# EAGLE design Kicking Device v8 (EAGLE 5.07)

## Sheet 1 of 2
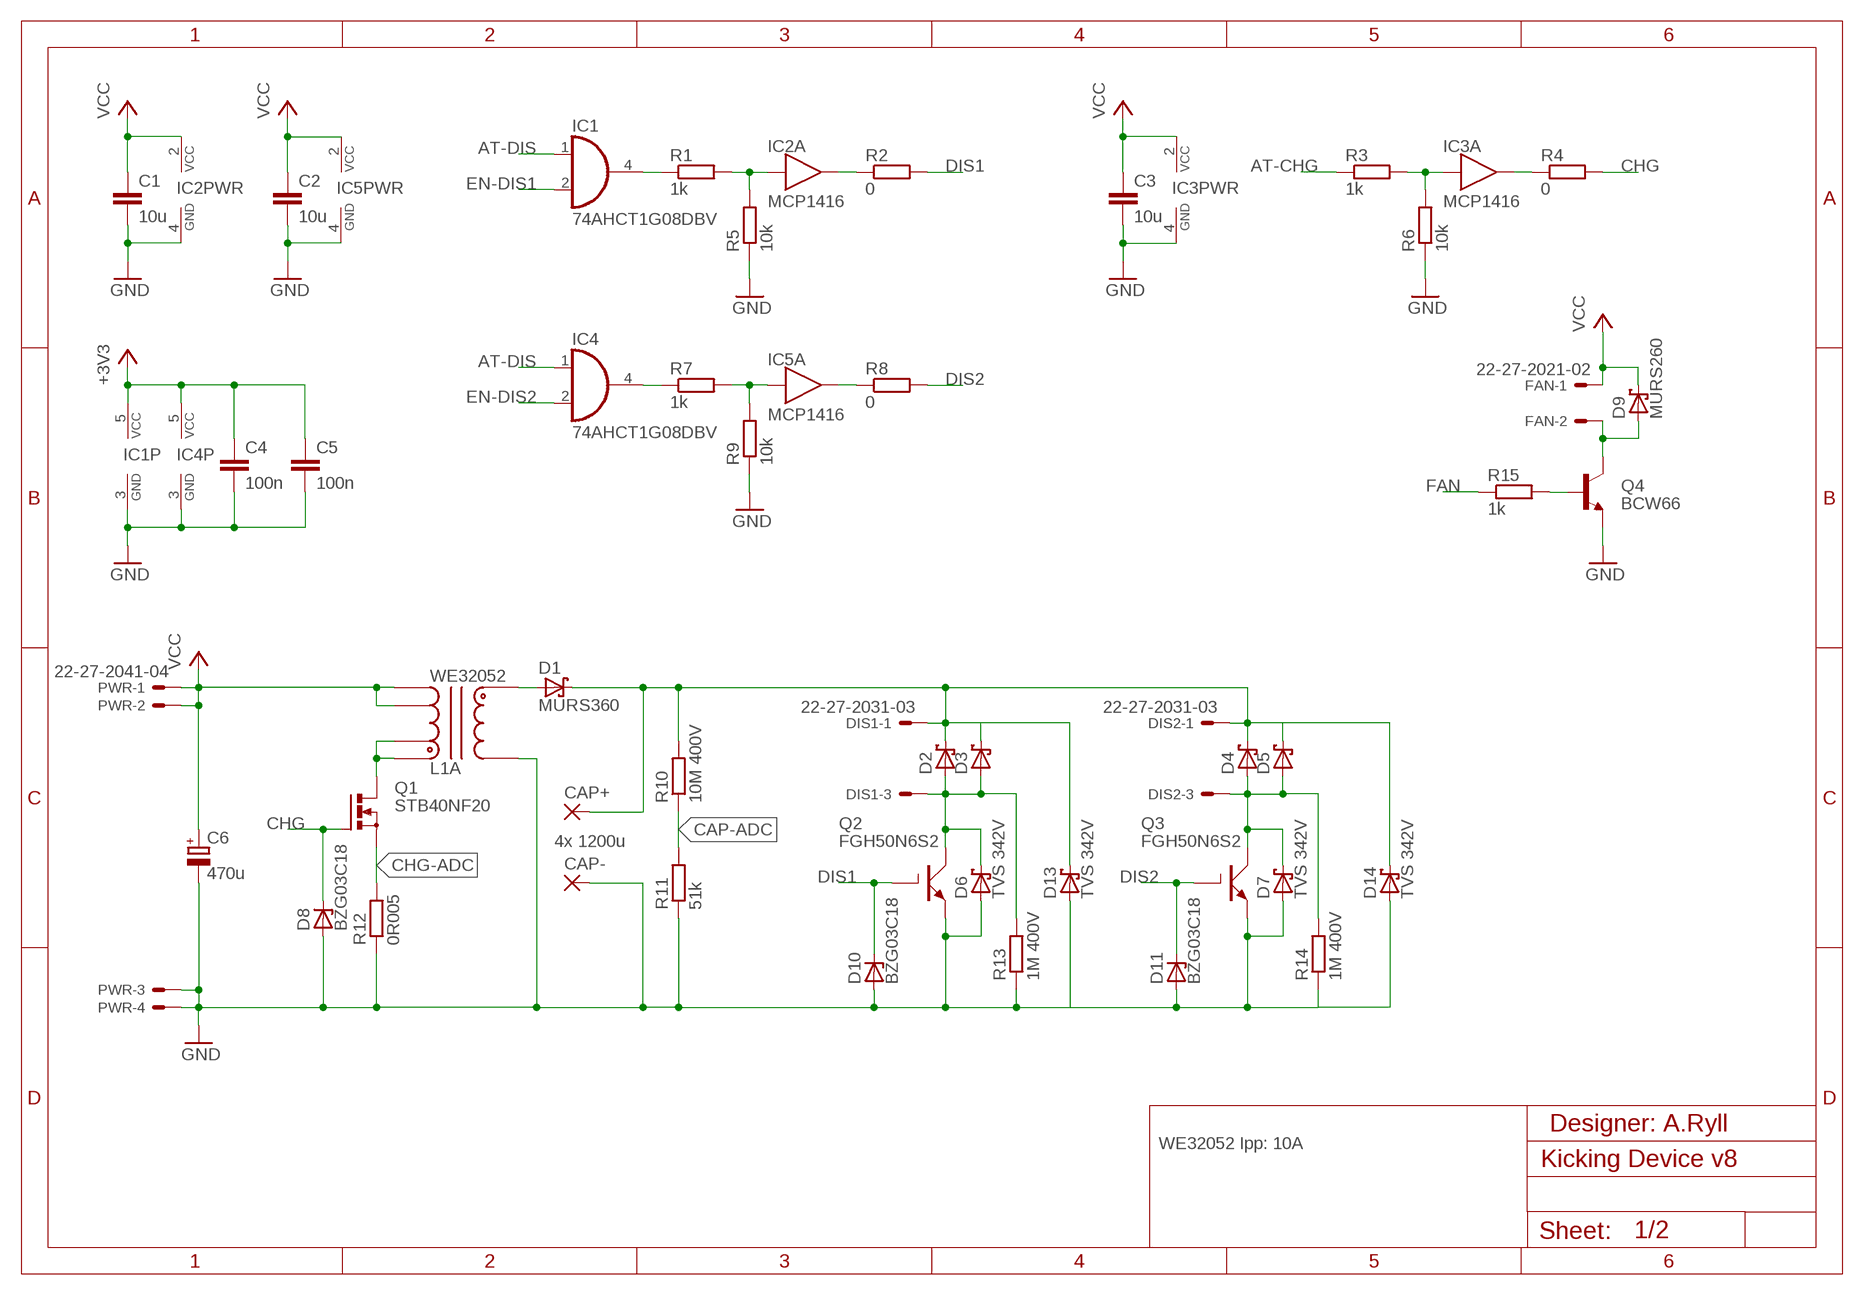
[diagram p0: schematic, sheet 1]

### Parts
C1  10u  C-EUC0805  [C0805]
C2  10u  C-EUC0805  [C0805]
C3  10u  C-EUC0805  [C0805]
C4  100n  C-EUC0805  [C0805]
C5  100n  C-EUC0805  [C0805]
C6  470u  CPOL-EUG  [PANASONIC_G]
CAP+  WIREPAD3,17/1,3  WIREPAD2,54/1,5  [2,54/1,5]
CAP-  WIREPAD3,17/1,3  WIREPAD2,54/1,5  [2,54/1,5]
D1  MURS360  SCHOTTKY-DIODESMC  [SMC]
D2  SCHOTTKY-DIODEAC  [TO247AC]
D3  SCHOTTKY-DIODEAC  [TO247AC]
D4  SCHOTTKY-DIODEAC  [TO247AC]
D5  SCHOTTKY-DIODEAC  [TO247AC]
D6  TVS 342V  SCHOTTKY-DIODESMD  [SMB]
D7  TVS 342V  SCHOTTKY-DIODESMD  [SMB]
D8  BZG03C18  ZENER-DIODESMB  [SMB]
D9  MURS260  SCHOTTKY-DIODESMD  [SMB]
D10  BZG03C18  ZENER-DIODESMB  [SMB]
D11  BZG03C18  ZENER-DIODESMB  [SMB]
D13  TVS 342V  SCHOTTKY-DIODESMD  [SMB]
D14  TVS 342V  SCHOTTKY-DIODESMD  [SMB]
DIS1  22-27-2031-03  [6410-03]
DIS2  22-27-2031-03  [6410-03]
FAN  22-27-2021-02  [6410-02]
IC1  74AHCT1G08DBV  [SOT23-5]
IC2  MCP1416  [SOT23-5]
IC3  MCP1416  [SOT23-5]
IC4  74AHCT1G08DBV  [SOT23-5]
IC5  MCP1416  [SOT23-5]
L1  WE32052  [WE32052]
PWR  22-27-2041-04  [6410-04]
Q1  STB40NF20  NMOS-D2PAK  [D2PAK]
Q2  FGH50N6S2  IGBT-TO247  [TO247BV]
Q3  FGH50N6S2  IGBT-TO247  [TO247BV]
Q4  BCW66  BCW60SMD  [SOT23-BEC]
R1  1k  R-EU_R0805  [R0805]
R2  0  R-EU_R0805  [R0805]
R3  1k  R-EU_R0805  [R0805]
R4  0  R-EU_R0805  [R0805]
R5  10k  R-EU_R0805  [R0805]
R6  10k  R-EU_R0805  [R0805]
R7  1k  R-EU_R0805  [R0805]
R8  0  R-EU_R0805  [R0805]
R9  10k  R-EU_R0805  [R0805]
R10  10M 400V  R-EU_R1206  [R1206]
R11  51k  R-EU_R0805  [R0805]
R12  0R005  R-EU_R2512  [R2512]
R13  1M 400V  R-EU_R1206  [R1206]
R14  1M 400V  R-EU_R1206  [R1206]
R15  1k  R-EU_R0805  [R0805]

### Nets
400-HIGH: D1.A L1.1
+3V3: C4.1 C5.1 IC1.5(VCC) IC4.5(VCC) ; also sheet 2
AT-CHG: R3.1 ; also sheet 2
AT-DIS: IC1.1(I0) IC4.1(I0) ; also sheet 2
CAP-ADC: R10.1 R11.2 ; also sheet 2
CAPVCC [HV]: CAP+.P$1(P) D1.C D2.1(C) D3.1(C) D4.1(C) D5.1(C) D13.C D14.C DIS1.1 DIS2.1 R10.2
CHG: D8.C Q1.1(G) R4.2
CHG-: L1.6 L1.7 Q1.2(D)
CHG-ADC: Q1.3(S) R12.2 ; also sheet 2
DIS1: D10.C Q2.1(G) R2.2
DIS1-SW [HV]: D2.3(A) D3.3(A) D6.C DIS1.3 Q2.2(C) R13.2
DIS2: D11.C Q3.1(G) R8.2
DIS2-SW [HV]: D4.3(A) D5.3(A) D7.C DIS2.3 Q3.2(C) R14.2
EN-DIS1: IC1.2(I1) ; also sheet 2
EN-DIS2: IC4.2(I1) ; also sheet 2
FAN: R15.1 ; also sheet 2
GND: C1.2 C2.2 C3.2 C4.2 C5.2 C6.- CAP-.P$1(P) D6.A D7.A D8.A D10.A D11.A D13.A D14.A IC1.3(GND) IC2.4(PWR:GND) IC3.4(PWR:GND) IC4.3(GND) IC5.4(PWR:GND) L1.10 PWR.3 PWR.4 Q2.3(E) Q3.3(E) Q4.E R5.1 R6.1 R9.1 R11.1 R12.1 R13.1 R14.1 ; also sheet 2
N$1: IC1.4(O) R1.1
N$2: IC2.3(A:IN) R1.2 R5.2
N$3: IC3.3(A:IN) R3.2 R6.2
N$5: IC2.5(A:OUT) R2.1
N$6: D9.A FAN.2 Q4.C
N$11: IC5.3(A:IN) R7.2 R9.2
N$12: Q4.B R15.2
N$13: IC4.4(O) R7.1
N$17: IC5.5(A:OUT) R8.1
N$19: IC3.5(A:OUT) R4.1
VCC: C1.1 C2.1 C3.1 C6.+ D9.C FAN.1 IC2.2(PWR:VCC) IC3.2(PWR:VCC) IC5.2(PWR:VCC) L1.4 L1.5 PWR.1 PWR.2
Unconnected: DIS1.2 DIS2.2

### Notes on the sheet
- 4x 1200u
- Designer: A.Ryll
- WE32052 Ipp: 10A

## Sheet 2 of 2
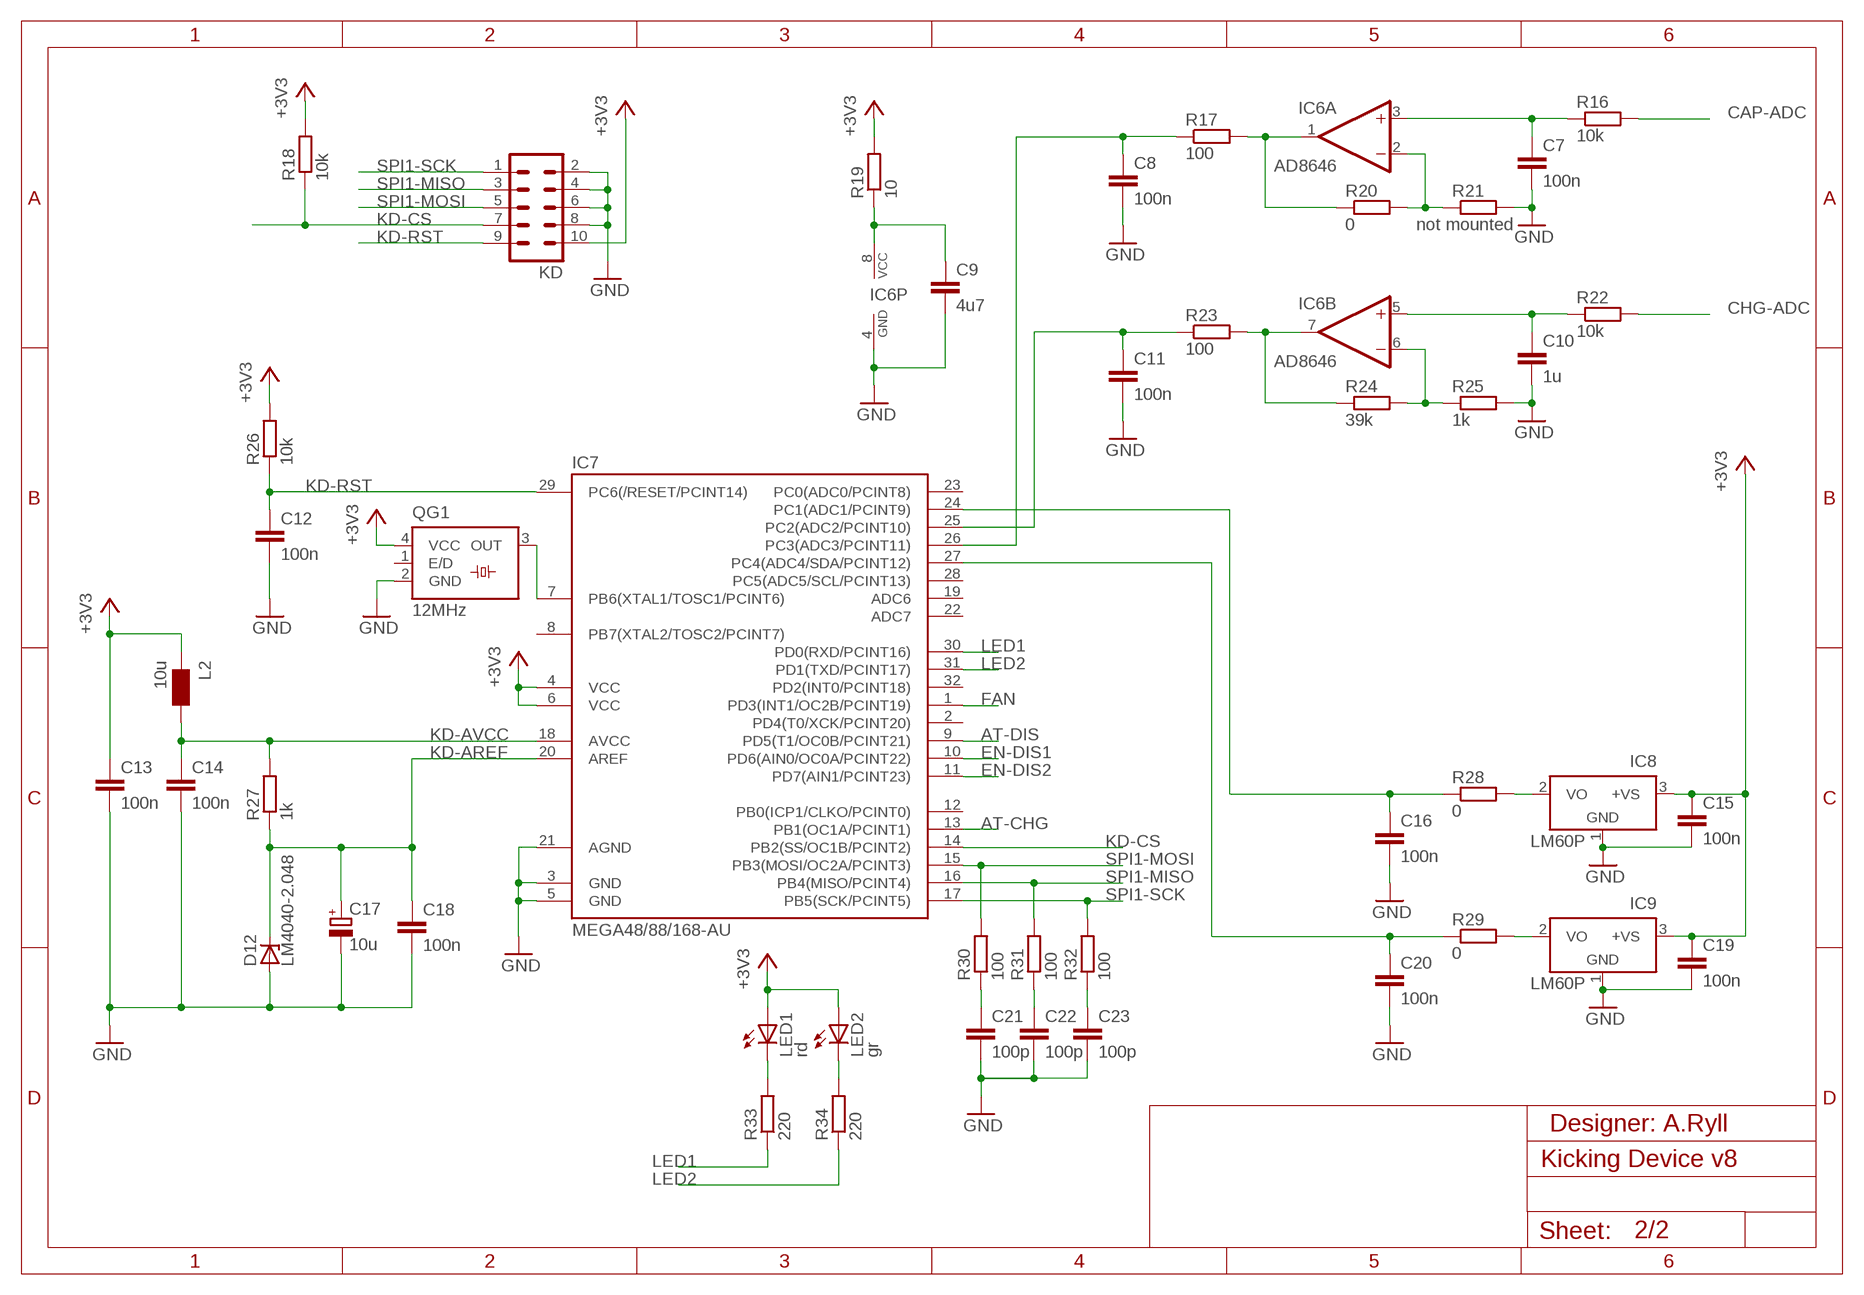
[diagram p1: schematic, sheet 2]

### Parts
C7  100n  C-EUC0805  [C0805]
C8  100n  C-EUC0805  [C0805]
C9  4u7  C-EUC0805  [C0805]
C10  1u  C-EUC0805  [C0805]
C11  100n  C-EUC0805  [C0805]
C12  100n  C-EUC0805  [C0805]
C13  100n  C-EUC0805  [C0805]
C14  100n  C-EUC0805  [C0805]
C15  100n  C-EUC0805  [C0805]
C16  100n  C-EUC0805  [C0805]
C17  10u  CPOL-EUC/6032-28W  [C/6032-28W]
C18  100n  C-EUC0805  [C0805]
C19  100n  C-EUC0805  [C0805]
C20  100n  C-EUC0805  [C0805]
C21  100p  C-EUC0805  [C0805]
C22  100p  C-EUC0805  [C0805]
C23  100p  C-EUC0805  [C0805]
D12  LM4040-2.048  ZENER-DIODELM4040  [SOT23]
IC6  AD8646  AD-OP2S  [SOIC8]
IC7  MEGA48/88/168-AU  [TQFP32-08]
IC8  LM60P  [TO92]
IC9  LM60P  [TO92]
KD  ML10  [ML10]
L2  10u  WE-MI_0805  [0805]
LED1  rd  LEDCHIP-LED0805  [CHIP-LED0805]
LED2  gr  LEDCHIP-LED0805  [CHIP-LED0805]
QG1  12MHz  SM77H  [SM77H]
R16  10k  R-EU_R0805  [R0805]
R17  100  R-EU_R0805  [R0805]
R18  10k  R-EU_R0805  [R0805]
R19  10  R-EU_R0805  [R0805]
R20  0  R-EU_R0805  [R0805]
R21  not mounted  R-EU_R0805  [R0805]
R22  10k  R-EU_R0805  [R0805]
R23  100  R-EU_R0805  [R0805]
R24  39k  R-EU_R0805  [R0805]
R25  1k  R-EU_R0805  [R0805]
R26  10k  R-EU_R0805  [R0805]
R27  1k  R-EU_R0805  [R0805]
R28  0  R-EU_R0805  [R0805]
R29  0  R-EU_R0805  [R0805]
R30  100  R-EU_R0805  [R0805]
R31  100  R-EU_R0805  [R0805]
R32  100  R-EU_R0805  [R0805]
R33  220  R-EU_R0805  [R0805]
R34  220  R-EU_R0805  [R0805]

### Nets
+3V3: C13.1 C15.1 C19.1 IC7.4(VCC) IC7.6(VCC) IC8.3(+VS) IC9.3(+VS) KD.10 L2.1 LED1.A LED2.A QG1.4(VCC) R18.2 R19.2 R26.2 ; also sheet 1
AT-CHG: IC7.13(PB1(OC1A/PCINT1)) ; also sheet 1
AT-DIS: IC7.9(PD5(T1/OC0B/PCINT21)) ; also sheet 1
CAP-ADC: R16.2 ; also sheet 1
CHG-ADC: R22.2 ; also sheet 1
EN-DIS1: IC7.10(PD6(AIN0/OC0A/PCINT22)) ; also sheet 1
EN-DIS2: IC7.11(PD7(AIN1/PCINT23)) ; also sheet 1
FAN: IC7.1(PD3(INT1/OC2B/PCINT19)) ; also sheet 1
GND: C7.2 C8.2 C9.2 C10.2 C11.2 C12.2 C13.2 C14.2 C15.2 C16.2 C17.- C18.2 C19.2 C20.2 C21.2 C22.2 C23.2 D12.2(A) IC6.4(P:GND) IC7.3(GND) IC7.5(GND) IC7.21(AGND) IC8.1(GND) IC9.1(GND) KD.2 KD.4 KD.6 KD.8 QG1.2(GND) R21.2 R25.2 ; also sheet 1
KD-AREF: C17.+ C18.1 D12.1(C) IC7.20(AREF) R27.1
KD-AVCC: C14.1 IC7.18(AVCC) L2.2 R27.2
KD-CS: IC7.14(PB2(SS/OC1B/PCINT2)) KD.7 R18.1
KD-RST: C12.1 IC7.29(PC6(/RESET/PCINT14)) KD.9 R26.1
LED1: IC7.30(PD0(RXD/PCINT16)) R33.1
LED2: IC7.31(PD1(TXD/PCINT17)) R34.1
N$4: LED1.C R33.2
N$8: LED2.C R34.2
N$10: IC8.2(VO) R28.2
N$14: IC9.2(VO) R29.2
N$15: C9.1 IC6.8(P:VCC) R19.1
N$18: C21.1 R30.1
N$23: C7.1 IC6.3(A:+IN) R16.1
N$24: IC6.1(A:OUT) R17.2 R20.1
N$25: IC6.2(A:-IN) R20.2 R21.1
N$28: C16.1 IC7.24(PC1(ADC1/PCINT9)) R28.1
N$31: C22.1 R31.1
N$32: C20.1 IC7.27(PC4(ADC4/SDA/PCINT12)) R29.1
N$36: C8.1 IC7.26(PC3(ADC3/PCINT11)) R17.1
N$38: C23.1 R32.1
N$39: C10.1 IC6.5(B:+IN) R22.1
N$40: IC6.6(B:-IN) R24.2 R25.1
N$41: C11.1 IC7.25(PC2(ADC2/PCINT10)) R23.1
N$42: IC6.7(B:OUT) R23.2 R24.1
SPI1-MISO: IC7.16(PB4(MISO/PCINT4)) KD.3 R31.2
SPI1-MOSI: IC7.15(PB3(MOSI/OC2A/PCINT3)) KD.5 R30.2
SPI1-SCK: IC7.17(PB5(SCK/PCINT5)) KD.1 R32.2
XTAL: IC7.7(PB6(XTAL1/TOSC1/PCINT6)) QG1.3(OUT)
Unconnected: IC7.2(PD4(T0/XCK/PCINT20)) IC7.8(PB7(XTAL2/TOSC2/PCINT7)) IC7.12(PB0(ICP1/CLKO/PCINT0)) IC7.19(ADC6) IC7.22(ADC7) IC7.23(PC0(ADC0/PCINT8)) IC7.28(PC5(ADC5/SCL/PCINT13)) IC7.32(PD2(INT0/PCINT18)) QG1.1(E/D)

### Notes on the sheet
- Designer: A.Ryll

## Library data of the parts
C1-C5 C7-C16 C18-C23 = rcl:C-EU: CAPACITOR, European symbol
C6 C17 = rcl:CPOL-EU: POLARIZED CAPACITOR, European symbol
CAP+ CAP- = Marvin:WIREPAD: Wire PAD connect wire on PCB
D1 D6 D7 D9 D13 D14 = diode:SCHOTTKY-DIODE: Schottky Diode
D2-D5 = Marvin:SCHOTTKY-DIODE: Schottky Diode
D8 D10 D11 = diode:ZENER-DIODE: Z-Diode
D12 = Marvin:ZENER-DIODE: Z-Diode
DIS1 DIS2 = con-molex:22-?-03: CONNECTOR wire to board 2.54 mm (.1 inch) pitch header
FAN = con-molex:22-?-02: CONNECTOR
IC1 IC4 = 74xx-little-de:74*1G08: 2-input AND gate
IC2 IC3 IC5 = Marvin:MCP1416
IC6 = Marvin:AD-OP2
IC7 = avr-6:MEGA48/88/168
IC8 IC9 = Marvin:LM60: LM60 Temperature Sensor -40°C to 125°C
KD = con-harting-ml:ML10: HARTING
L1 = Marvin:WE32052
L2 = wuerth-elektronik:WE-MI: SMD Multilayer Inductor WE-MI
LED1 LED2 = led:LED: LED
PWR = con-molex:22-?-04: CONNECTOR wire to board 2.54 mm (.1 inch) pitch header
Q1 = Marvin:NMOS-D2PAK
Q2 Q3 = Marvin:IGBT-TO247
Q4 = transistor-npn:BCW60*: NPN Transistor
QG1 = Marvin:SM77H: 3.3V CMOS Clock Oscillator Source: www.pletronics.com .. sm77h%203.3v.pdf
R1-R34 = rcl:R-EU_: RESISTOR, European symbol

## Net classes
0 default: width 0.152 mm, clearance 0.152 mm
1 HV: width 0.254 mm, drill 0.305 mm, clearance 1.524 mm to class 0, clearance 1.524 mm

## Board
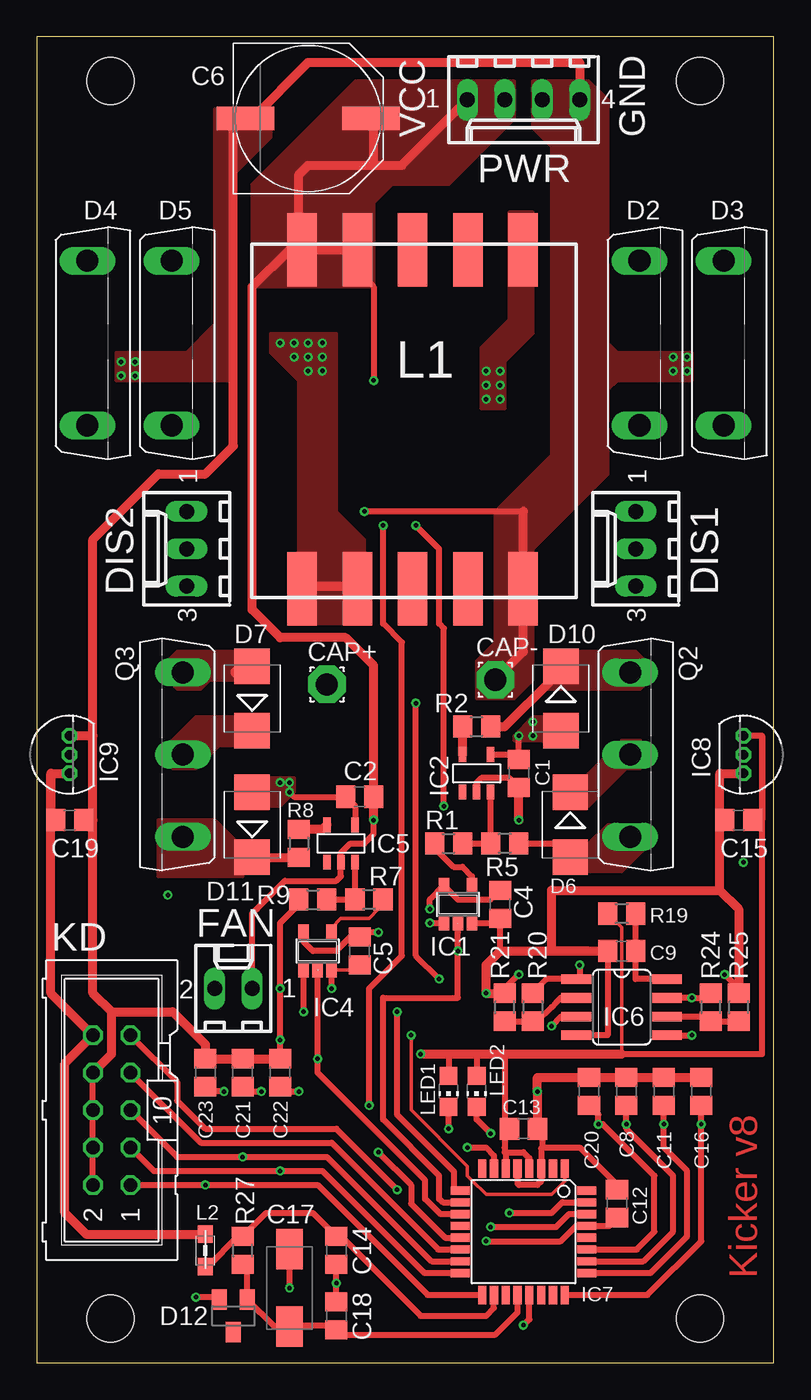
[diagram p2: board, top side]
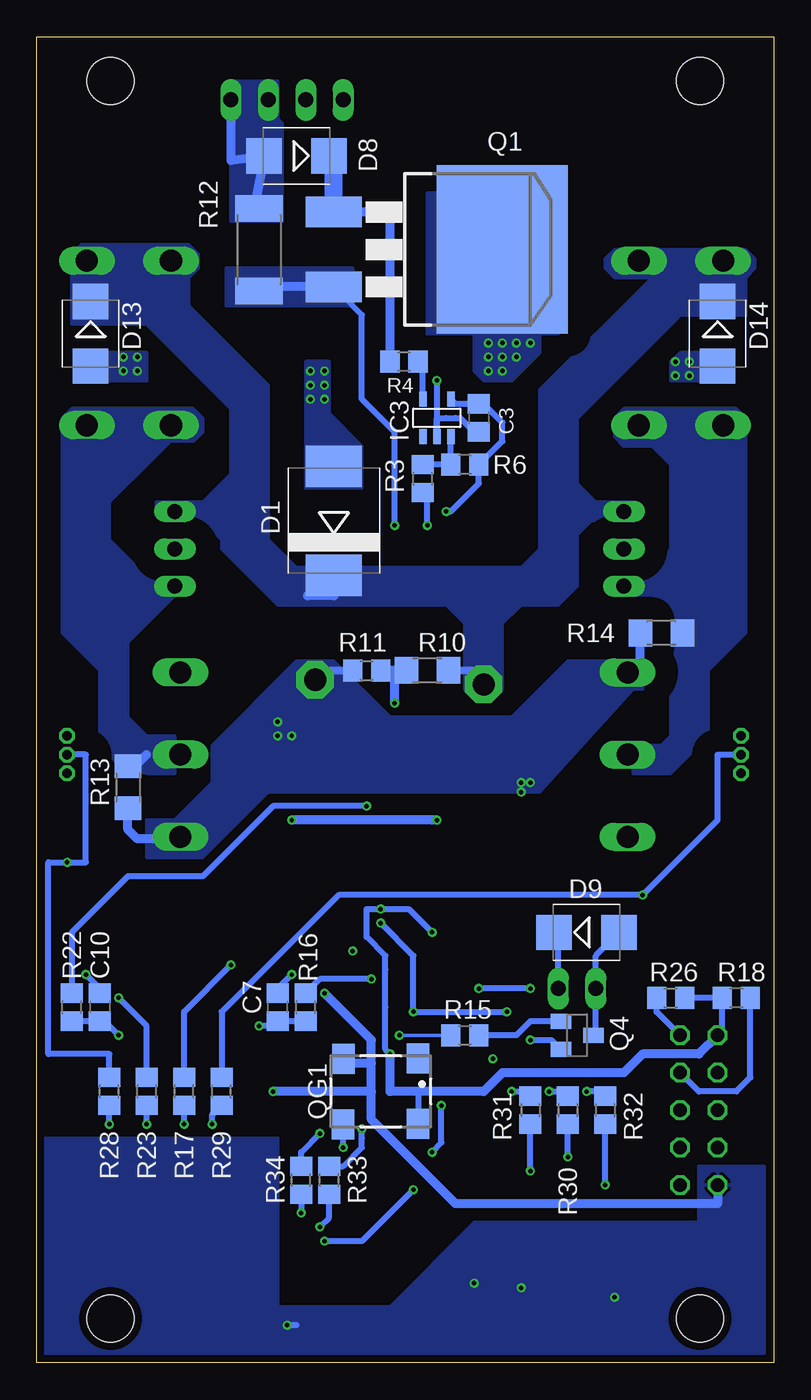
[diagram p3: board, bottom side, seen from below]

Size 50 x 90 mm. Coordinates in mm from the lower left corner, seen from the top.
Outline: 0,0 50,0 50,90 0,90 0,0
Copper layers (1*16): Top 0.035mm / dielectric 1.5mm / Bottom 0.035mm
Design rules "PCB-POOL *": minimum track width 6mil, minimum drill 12mil, track to track 6mil, track to pad 6mil, pad to pad 6mil, via to via 6mil, smd to smd 6mil, copper to edge 20mil, drill to drill 8mil, minimum pad ring 8mil, minimum via ring 6mil, stop-mask expansion 3mil, vias tented up to drill 0mil, thermal gap 8mil
Holes 3.2 mm at 45,3 5,3 5,87 45,87

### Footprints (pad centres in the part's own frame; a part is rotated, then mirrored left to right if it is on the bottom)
C0805 = smd 1.3 x 1.5: 1 -0.95,0; 2 0.95,0
PANASONIC_G = smd 3.9 x 1.6: + 4.25,0; - -4.25,0
C/6032-28W = smd 2.75 x 1.8: + 2.625,0; - -2.625,0
2,54/1,5 = drill 1.5 pad 2.54 octagon: P$1 0,0
SMC = smd 2.8 x 3.8: A 3.7,0; C -3.7,0
TO247AC = drill 1.499 long: 1 -5.588,-2.921; 3 5.588,-2.921
SMB = smd 2.4 x 2.4: A 2.2,0; C -2.2,0
SOT23 = smd 1 x 1.4: 1 -0.95,-1.1; 2 0.95,-1.1; 3 0,1.1
6410-03 = drill 1.016 long: 1 2.54,0; 2 0,0; 3 -2.54,0
6410-02 = drill 1.016 long: 1 1.27,0; 2 -1.27,0
SOT23-5 = smd 0.69 x 0.99: 1 -0.95,-1.29; 2 0,-1.29; 3 0.95,-1.29; 4 0.95,1.3; 5 -0.95,1.3
SOT23-5' = smd 1.016 x 0.508: 1 -1.27,0.953; 2 -1.27,0; 3 -1.27,-0.953; 4 1.27,-0.953; 5 1.27,0.953
SOIC8 = smd 0.66 x 2.032: 1 -1.905,-3.073; 2 -0.635,-3.073; 3 0.635,-3.073; 4 1.905,-3.073; 5 1.905,3.073; 6 0.635,3.073; 7 -0.635,3.073; 8 -1.905,3.073
TQFP32-08 = smd 1.27 x 0.559: 1 -4.293,2.8; 2 -4.293,2; 3 -4.293,1.2; 4 -4.293,0.4; 5 -4.293,-0.4; 6 -4.293,-1.2; 7 -4.293,-2; 8 -4.293,-2.8; 17 4.293,-2.8; 18 4.293,-2; 19 4.293,-1.2; 20 4.293,-0.4; 21 4.293,0.4; 22 4.293,1.2; 23 4.293,2; 24 4.293,2.8 | smd 0.559 x 1.27: 9 -2.8,-4.293; 10 -2,-4.293; 11 -1.2,-4.293; 12 -0.4,-4.293; 13 0.4,-4.293; 14 1.2,-4.293; 15 2,-4.293; 16 2.8,-4.293; 25 2.8,4.293; 26 2,4.293; 27 1.2,4.293; 28 0.4,4.293; 29 -0.4,4.293; 30 -1.2,4.293; 31 -2,4.293; 32 -2.8,4.293
TO92 = drill 0.65 pad 0.813 octagon: 1 1.27,0; 2 0,0; 3 -1.27,0
ML10 = drill 0.914 octagon: 1 -5.08,-1.27; 2 -5.08,1.27; 3 -2.54,-1.27; 4 -2.54,1.27; 5 0,-1.27; 6 0,1.27; 7 2.54,-1.27; 8 2.54,1.27; 9 5.08,-1.27; 10 5.08,1.27
WE32052 = smd 5 x 2: 1 -11.4,7.6; 2 -11.4,3.85; 3 -11.4,0.1; 4 -11.4,-3.65; 5 -11.4,-7.4; 6 11.6,-7.4; 7 11.6,-3.65; 8 11.6,0.1; 9 11.6,3.85; 10 11.6,7.6
0805 = smd 1.2 x 1: 1 -1.1,0; 2 1.1,0
CHIP-LED0805 = smd 1.2 x 1.2: A 0,-1.05; C 0,1.05
6410-04 = drill 1.016 long: 1 3.81,0; 2 1.27,0; 3 -1.27,0; 4 -3.81,0
D2PAK = smd 2.083 x 3.81: 1 -2.54,-8.89; 3 2.54,-8.89 | smd 11.43 x 8.89: 2 0,2.54
TO247BV = drill 1.499 long: 1 -5.588,-2.921; 2 0,-2.921; 3 5.588,-2.921
SOT23-BEC = smd 1 x 1.4: B -0.95,-1.1; C 0,1.1; E 0.95,-1.1
SM77H = smd 1.524 x 2.032: 1 -2.545,-2.232; 2 2.535,-2.212; 3 2.545,2.232; 4 -2.535,2.212
R0805 = smd 1.3 x 1.5: 1 -0.95,0; 2 0.95,0
R1206 = smd 1.6 x 1.803: 1 -1.422,0; 2 1.422,0
R2512 = smd 1.8 x 3.2: 1 -2.8,0; 2 2.8,0

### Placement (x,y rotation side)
C1  32.7,40.01 90 top
C2  21.91,38.42 180 top
C3  20,64.14 90 bottom
C4  31.43,31.11 270 top
C5  21.91,27.94 270 top
C6  18.41,84.45 0 top
C7  33.66,24.13 90 bottom
C8  40.01,18.41 90 top
C9  39.69,27.94 180 top
C10  45.72,24.13 90 bottom
C11  42.55,18.41 90 top
C12  39.37,10.79 90 top
C13  33.02,15.88 0 top
C14  20.32,7.62 270 top
C15  47.62,36.83 180 top
C16  45.09,18.41 90 top
C17  17.14,5.08 270 top
C18  20.32,3.17 90 top
C19  2.22,36.83 0 top
C20  37.47,18.41 90 top
C21  13.97,19.68 90 top
C22  16.51,19.68 90 top
C23  11.43,19.68 90 top
CAP+  19.68,46.04 0 top
CAP-  31.11,46.35 0 top
D1  29.84,57.15 90 bottom
D2  43.81,69.22 270 top
D3  49.53,69.22 270 top
D4  6.35,69.22 270 top
D5  12.06,69.22 270 top
D6  36.2,36.51 270 top
D7  14.61,45.09 90 top
D8  32.38,81.92 180 bottom
D9  12.7,29.21 0 bottom
D10  35.56,45.09 270 top
D11  14.61,36.51 90 top
D12  13.34,3.17 180 top
D13  46.35,69.85 270 bottom
D14  3.81,69.85 270 bottom
DIS1  40.64,55.24 90 top
DIS2  10.16,55.24 90 top
FAN  13.34,25.4 0 top
IC1  28.57,31.11 0 top
IC2  MCP1416  [SOT23-5']  29.84,40.01 90 top
IC3  MCP1416  [SOT23-5']  22.86,64.14 90 bottom
IC4  19.05,27.94 0 top
IC5  MCP1416  [SOT23-5']  20.64,35.24 90 top
IC6  39.69,24.13 270 top
IC7  33.02,8.89 270 top
IC8  47.94,41.27 270 top
IC9  2.22,41.27 90 top
KD  5.08,17.14 90 top
L1  25.4,64.14 270 top
L2  11.43,7.62 270 top
LED1  27.94,18.41 180 top
LED2  29.84,18.41 180 top
PWR  33.02,85.72 180 top
Q1  20.95,75.56 270 bottom
Q2  43.18,41.27 270 top
Q3  6.99,41.27 90 top
Q4  13.34,22.23 270 bottom
QG1  26.67,18.41 180 bottom
R1  27.94,35.24 0 top
R2  29.84,43.18 0 top
R3  23.81,60.01 90 bottom
R4  25.08,67.94 180 bottom
R5  31.75,35.24 180 top
R6  20.95,60.96 180 bottom
R7  22.54,31.43 180 top
R8  17.78,35.24 270 top
R9  18.73,31.43 0 top
R10  23.5,46.99 0 bottom
R11  27.62,46.99 0 bottom
R12  34.92,75.56 270 bottom
R13  43.81,39.05 90 bottom
R14  7.62,49.53 0 bottom
R15  20.95,22.23 0 bottom
R16  31.75,24.13 90 bottom
R17  40.01,18.41 90 bottom
R18  2.54,24.77 180 bottom
R19  39.69,30.48 180 top
R20  33.66,24.13 270 top
R21  31.75,24.13 90 top
R22  47.62,24.13 90 bottom
R23  42.55,18.41 90 bottom
R24  45.72,24.13 270 top
R25  47.62,24.13 90 top
R26  6.99,24.77 0 bottom
R27  13.97,7.62 90 top
R28  45.09,18.41 90 bottom
R29  37.47,18.41 90 bottom
R30  13.97,17.14 270 bottom
R31  16.51,17.14 270 bottom
R32  11.43,17.14 270 bottom
R33  30.16,12.38 90 bottom
R34  32.07,12.38 90 bottom

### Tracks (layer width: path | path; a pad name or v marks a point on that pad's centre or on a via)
400-HIGH  (via drill 0.3)
  Top 0.61: L1.1 33.02,75.52
  other vias: 31.43,65.41 30.48,65.41 30.48,66.36 31.43,66.36 31.43,67.31 30.48,67.31
  pour Top (no thermals): 32.07,78.11 32.07,70.8 30.16,68.9 30.16,64.77 31.75,64.77 31.75,67.94 33.66,69.85 33.66,78.11
  pour Bottom (no thermals): 31.75,59.37 27.94,59.37 27.94,62.23 30.16,64.45 30.16,67.94 31.75,67.94
+3V3  (via drill 0.3)
  Top 0.254: 39.69,20.95 39.69,29.53 R19.2 | C5.1 21.27,28.89 | IC4.5
  Top 0.406: 49.21,42.55 49.21,36.83 C15.1 | 49.21,42.55 IC8.3 | 49.21,42.55 49.21,20.95 39.69,20.95 | IC7.4 33.42,13.89 33.02,14.29 31.75,14.29 | IC7.6 31.82,14.22 31.75,14.29 | 31.75,14.29 31.75,14.61 31.75,15.87 C13.1 31.75,15.88 31.75,20.95 | 29.84,20.95 LED2.A | 27.94,20.95 LED1.A | 21.27,28.89 20.32,27.94 18.73,27.94 18.1,28.57 IC4.5 | v26.67,30.8 26.67,31.46 IC1.5 27.62,32.38 28.57,31.43 30.8,31.43 C4.1 | C5.1 21.91,29.21 22.86,29.21 v23.18,29.21
  Top 0.61: 0.95,40.01 0.95,36.83 C19.1 | 0.95,40.01 IC9.3 | v26.04,20.95 27.94,20.95 29.84,20.95 31.75,20.95 39.69,20.95 | 0.95,40.01 0.95,25.08 KD.10 1.91,20.32 1.91,10.16 3.35,8.72 L2.1
  Bottom 0.406: R26.2 R18.2 3.49,22.55 KD.10 | QG1.4 24.13,16.52 24.13,18.41 | v26.04,20.95 26.35,21.27 26.35,24.13 26.35,26.67 26.35,27.62 27.62,28.89 27.62,30.8 v26.67,30.8 24.77,30.8 v23.18,29.21
  Bottom 0.61: KD.10 5.08,20.95 8.89,20.95 10.16,19.68 18.41,19.68 19.68,18.41 24.13,18.41 26.04,18.41 v26.04,20.95
AT-CHG  (via drill 0.3)
  Top 0.406: v23.5,56.83 23.5,50.16 24.77,48.9 24.77,27.62 22.54,25.4 v22.54,17.46 | IC7.13 27.7,8.49 25.4,10.79 25.4,12.06 v23.18,14.29
  Bottom 0.406: v23.18,14.29 22.54,14.92 v22.54,17.46 | v23.5,56.83 23.5,58.74 R3.1
AT-DIS  (via drill 0.3)
  Top 0.406: v24.45,23.81 24.45,17.46 24.45,16.83 25.4,15.88 28.32,12.96 28.32,11.69 IC7.9 | v18.1,23.81 IC4.1 | v26.67,29.84 27.61,29.84 IC1.1
  Bottom 0.406: v18.1,23.81 v24.45,23.81 24.45,27.62 v26.67,29.84
CAP-ADC  (via drill 0.3)
  Top 0.406: v27.3,26.04 25.72,27.62 v25.72,44.77
  Bottom 0.406: v27.3,26.04 30.8,26.04 31.43,25.4 R16.2
  Bottom 0.61: 25.4,46.99 R10.1 | 25.4,46.99 R11.2 | v25.72,44.77 25.72,46.67 25.4,46.99
CAPVCC
  Bottom 0.508: R10.2 20.32,46.99 CAP+.P$1
  Bottom 0.61: D1.C 31.64,52.07 29.84,52.07
  pour Bottom (no thermals): 11.43,74.93 11.43,74.3 10.79,73.66 8.26,73.66 15.88,66.04 15.88,55.24 17.14,53.98 32.38,53.98 34.29,55.88 34.29,66.36 39.69,71.75 39.69,73.66 39.05,74.3 39.05,75.25 39.69,75.88 46.99,75.88 47.62,75.25 47.62,70.48 42.55,70.48 36.83,64.77 36.83,60.33 38.73,58.42 41.91,58.42 41.91,57.15 38.73,57.15 37.47,55.88 37.47,55.24 33.66,51.44 22.23,51.44 20.95,50.16 20.95,45.72 18.41,45.72 18.41,50.16 17.14,51.44 14.61,51.44 13.34,52.7 13.34,56.2 12.38,57.15 9.53,57.15 9.53,58.42 12.06,58.42 13.34,59.69 13.34,64.14 6.35,71.12 1.91,71.12 1.91,73.66 1.27,74.3 1.27,74.93 1.91,75.56 10.79,75.56
CHG
  Bottom 0.61: Q1.1 26.04,78.11 26.04,70.17 26.03,70.16 R4.2 | 29.84,81.58 D8.C
  Bottom 1.219: Q1.1 29.84,81.58
CHG-  (via drill 0.3)
  Top 0.61: L1.7 21.12,52.53 20.95,52.7 18.17,52.7 L1.6 18,53.34 17.78,53.34
  Bottom 0.61: Q1.2 17.78,73.66
  other vias: 18.41,68.26 17.46,69.22 17.46,68.26 16.51,69.22 19.37,69.22 18.41,69.22 19.37,67.31 19.37,68.26 18.41,67.31
  pour Bottom (no thermals): 14.61,79.38 14.61,69.85 15.88,69.85 15.88,68.58 17.78,66.67 19.68,66.67 20.32,67.31 20.32,69.85 23.5,69.85 23.5,79.38
  pour Top (no thermals): 22.23,50.16 17.78,50.16 17.78,66.67 15.88,68.58 15.88,69.85 20.32,69.85 20.32,57.78 22.23,55.88
CHG-ADC  (via drill 0.3)
  Top 0.406: v25.72,56.83 27.3,55.24 27.3,50.16 27.62,49.85 v27.62,37.78
  Bottom 0.406: v25.72,56.83 25.72,62.55 25.72,63.18 27.94,65.41 27.94,71.12 29.21,72.39 29.21,73.03 | v27.62,37.78 33.97,37.78 38.73,33.02 43.81,33.02 47.62,29.21 47.62,25.4 R22.2
  Bottom 0.61: R12.2 35.56,73.03 Q1.3 29.21,73.03
  pour Bottom (no thermals): 28.57,74.3 37.15,74.3 37.15,71.75 28.57,71.75
DIS1
  Top 0.406: 34.92,46.35 35.37,46.35 35.79,46.78
  Top 0.559: D10.C 35.79,46.78 35.85,46.65
  Top 0.61: R2.2 31.75,43.18 34.92,46.35
  pour Top (no thermals): 34.61,48.26 40.64,48.26 41.91,46.99 41.91,46.67 40.96,45.72 34.61,45.72
DIS1-SW
  Bottom 0.61: R13.2 43.35,40.47 42.55,41.27
  pour Bottom (no thermals): 38.73,63.18 39.37,62.55 40.96,62.55 45.09,58.42 45.09,55.88 42.55,53.34 40.64,53.34 40.64,52.07 43.81,48.9 43.81,43.81 42.55,42.55 40.64,42.55 40.64,40.01 43.81,40.01 45.72,41.91 45.72,46.99 48.26,49.53 48.26,64.14 47.62,64.77 39.37,64.77 38.73,64.14
  pour Top (no thermals): 35.24,39.69 37.15,39.69 39.69,42.23 40.96,42.23 41.91,41.27 40.96,40.32 40.01,40.32 37.47,37.78 35.24,37.78
DIS2
  Top 0.406: D11.C 14.62,34.29
  Top 0.61: D11.C 13.97,34.29 | 14.62,34.29 R8.2
  pour Top (no thermals): 13.97,33.02 8.26,33.02 8.26,36.83 12.06,36.83 13.97,34.92
DIS2-SW
  pour Bottom (no thermals): 10.16,62.23 8.26,62.23 6.99,60.96 6.99,55.24 8.89,53.34 10.79,53.34 10.79,52.07 8.89,52.07 6.99,50.16 6.99,42.55 7.62,41.91 9.53,41.91 9.53,40.01 6.99,40.01 4.45,42.55 4.45,46.99 1.91,49.53 1.91,63.5 1.91,64.14 2.54,64.77 10.16,64.77 10.79,64.14 10.79,62.87
  pour Top (no thermals): 8.26,41.27 10.79,43.81 14.61,43.81 14.61,41.91 12.38,41.91 10.79,40.32 9.21,40.32
EN-DIS1  (via drill 0.3)
  Top 0.406: IC7.10 27.53,10.89 27.3,11.11 27.3,12.7 23.5,16.51 23.5,24.77 28.57,24.77 v28.57,27.94 28.57,28.57 28.57,29.21 IC1.2
EN-DIS2  (via drill 0.3)
  Top 0.406: IC7.11 27.38,10.09 26.35,11.11 26.35,12.38 22.86,15.88 19.05,19.68 v19.05,20.64 19.05,24.13 IC4.2
FAN  (via drill 0.3)
  Top 0.254: IC7.1 35.82,12.32 34.92,11.43 30.48,11.43 29.53,12.38 29.21,12.7 29.21,13.34 25.4,17.14 v25.4,22.23
  Bottom 0.254: v25.4,22.23 23.5,22.23 23.18,22.23 R15.1
GND  (via drill 0.3)
  Top 0.254: C5.2 21.25,26.65 IC4.3
  Top 0.406: C9.2 38.73,22.23 IC6.4 | R25.2 47.62,25.4 v46.67,26.35 | v32.7,26.35 31.75,25.4 R21.2 | KD.8 KD.6 KD.4 KD.2 | IC7.21 33.42,2.94 v33.02,2.54 | C18.2 v20.32,5.4 C14.2 | v17.14,5.08 C17.- | D12.2 12.38,4.44 12.38,4.45 v10.79,4.45 | C12.2 39.37,12.06 36.83,14.61 34.29,14.61 | IC7.5 32.62,12.15 32.7,12.06 33.97,12.06 34.22,12.31 IC7.3 34.22,14.54 34.29,14.61 | 34.29,14.61 34.29,15.88 C13.2 | C22.2 v16.51,21.91 16.51,24.77 v16.51,25.4 16.51,29.84 17.78,31.12 R9.1 | IC5.4 21.59,37.78 C2.2 17.46,38.42 v17.14,38.73 | IC4.3 v20,25.4 | IC1.3 30.77,29.82 C4.2 31.43,27.94 | R5.1 35.27,35.24 D6.A | IC2.4 32.38,41.27 C1.2 v32.7,42.55 | 33.02,57.78 v22.23,57.78
  Top 0.508: C9.2
  Top 0.61: CAP-.P$1 33.02,48.26 33.02,52.52 L1.10 33.02,52.53 33.02,57.78 | 46.35,40.01 IC8.1 | 46.35,32.07 46.35,36.83 | 46.35,36.83 46.35,40.01 | 3.81,42.55 IC9.1 | 3.81,36.83 C19.2 | 46.35,36.83 C15.2 46.35,36.83 | KD.8 5.08,20.95 5.08,23.81 | 5.08,23.81 3.81,25.08 3.81,36.83 | 5.08,23.81 9.21,23.81 11.43,21.59 C23.2 C21.2 C22.2 | 37.47,27.94 31.43,27.94 30.48,26.99 v30.48,25.08 31.11,25.08 R21.2 | 37.47,27.94 34.92,27.94 34.92,32.07 46.35,32.07 | 37.47,27.94 C9.2 | C16.2 C11.2 C8.2 C20.2 33.97,19.36 v33.97,18.41 33.97,17.14 C13.2 | 46.35,32.07 47.62,30.8 R25.2 | D11.A 15.22,38.71 | PWR.4 36.83,88.27 18.41,88.27 14.61,84.45 C6.- 13.34,84.45 13.34,62.23 11.43,60.33 8.26,60.33 3.81,55.88 3.81,42.55 | 3.81,36.83 3.81,42.55 | 46.35,36.83 46.35,40.01 | 3.81,36.83 3.81,42.55
  Top 0.813: D7.A 13.55,46.86
  Bottom 0.406: v46.67,26.35 45.72,25.4 C10.2 | C7.2 33.65,25.4 33.66,25.4 v32.7,26.35 | 32.38,2.54 v33.02,2.54 | Q4.E 15.07,21.91 v16.51,21.91 | v16.51,25.4 v20,25.4 | IC3.4 21.59,65.08 C3.2 19.68,65.08 18.41,63.82 18.41,62.55 R6.1 20,59.69 21.91,57.78 v22.23,57.78
  Bottom 0.508: R11.1 30.48,46.99 CAP-.P$1
  Bottom 0.61: 27.3,18.41 27.3,20.32 | 27.3,20.32 29.2,20.32 QG1.2 29.21,20.32 27.3,20.32 | 27.3,18.41 27.3,16.51 21.59,10.79 3.81,10.79 KD.2 | 27.3,20.32 27.3,21.91 v30.48,25.08 | 27.3,18.41 v33.97,18.41 | R12.1 35.24,78.4 D8.A 36.83,81.62 PWR.4 | R13.1 43.81,36.2 43.18,35.56 40.39,35.56 Q2.3 | R14.1 9.04,47.41 Q3.3
  other vias: 16.51,39.37 33.66,42.55 17.14,39.37 33.66,43.5 5.71,67.94 6.67,67.94 5.71,66.99 6.67,66.99 44.13,68.26 43.18,68.26 44.13,67.31 43.18,67.31
  pour Bottom (no thermals): 8.89,47.62 13.97,47.62 17.78,43.81 26.04,43.81 29.84,47.62 32.38,47.62 38.1,41.91 38.1,39.37 40.64,36.83 42.55,36.83 42.55,34.29 38.73,34.29 34.29,38.73 15.88,38.73 9.53,45.72 8.89,45.72
  pour Top (no thermals): 29.84,47.62 31.11,48.9 31.11,57.78 34.92,61.59 34.92,82.55 33.66,83.82 33.66,87 37.47,87 38.73,85.72 38.73,69.22 39.37,68.58 44.45,68.58 44.45,66.67 39.37,66.67 38.73,66.04 38.73,60.33 33.66,55.24 33.66,46.35 32.38,45.09 29.84,45.09
  pour Bottom: 0.64,0.64 0.64,13.34 5.08,13.34 5.08,9.53 20.32,9.53 26.04,3.81 33.66,3.81 33.66,15.24 49.53,15.24 49.53,0.64
  pour Top (no thermals): 13.97,39.69 17.46,39.69 17.46,38.73 16.51,37.78 13.97,37.78
  pour Top (no thermals): 36.2,41.91 34.61,41.91 34.29,42.23 32.38,42.23 32.38,42.55 33.66,43.81 36.2,43.81
  pour Top (no thermals): 8.26,46.99 9.53,48.26 14.61,48.26 14.61,46.35 11.75,46.35 11.11,45.72 9.53,45.72
  pour Top (no thermals): 41.91,35.56 39.69,33.34 35.24,33.34 35.24,35.24 37.47,35.24 38.73,36.51 40.96,36.51
  pour Bottom (no thermals): 33.34,77.47 33.34,84.14 33.66,84.45 33.66,87 36.83,87 36.83,77.47
  pour Top (no thermals): 12.06,85.09 15.88,85.09 15.88,83.19 13.34,80.64 13.34,66.67 5.4,66.67 5.4,68.58 10.16,68.58 12.06,70.48
  pour Bottom (no thermals): 3.17,68.58 6.35,68.58 6.99,67.94 6.99,66.67 3.17,66.67
  pour Bottom (no thermals): 46.99,66.67 42.55,66.67 42.55,68.58 46.99,68.58
KD-AREF
  Top 0.406: IC7.20 32.62,3.41 31.11,1.91 20.64,1.91 C18.1 20,2.54 17.23,2.54 C17.+ 16.11,2.46 D12.1 14.29,6.36 R27.1
KD-AVCC
  Top 0.406: IC7.18 31.02,3.71 30.48,3.17 26.04,3.17 20.64,8.57 C14.1 18.73,10.16 15.56,10.16 R27.2 13.65,8.57 11.6,6.52 L2.2
KD-CS
  Top 0.406: IC7.14 27.23,7.69 20,14.92 11.11,14.92 KD.7
  Bottom 0.406: KD.7 5.08,18.41 2.54,18.41 1.59,19.36 R18.1
KD-RST  (via drill 0.3)
  Top 0.406: KD.9 9.53,19.05 9.53,17.78 11.43,15.88 20.32,15.88 v24.45,11.75 | C12.1 38.81,9.29 IC7.29 36.59,9.29 35.56,8.26 v30.48,8.26
  Bottom 0.406: KD.9 7.93,23.81 R26.1 | v24.45,11.75 27.94,8.26 v30.48,8.26
LED1  (via drill 0.3)
  Top 0.406: v30.8,9.21 35.24,9.21 36.12,10.09 IC7.30
  Bottom 0.406: v30.8,9.21 30.16,9.84 R33.1
LED2  (via drill 0.3)
  Top 0.406: v32.07,10.16 34.92,10.16 35.66,10.89 IC7.31
  Bottom 0.406: R34.1 v32.07,10.16
N$1
  Top 0.406: IC1.4 29.52,33.02 28.89,33.66 28.26,33.66 27.3,34.61 27.3,34.93 R1.1
N$2
  Top 0.406: IC2.3 R5.2 R1.2
N$3
  Bottom 0.406: IC3.3 R6.2 R3.2
N$4  (via drill 0.3)
  Top 0.406: v27.94,15.88 LED1.C
  Bottom 0.406: R33.2 29.21,13.34 27.94,14.61 27.94,15.24 v27.94,15.88
N$5
  Top 0.406: R2.1
  Top 0.61: IC2.5 R2.1
N$6
  Bottom 0.406: D9.A 12.06,27.64 FAN.2 12.06,22.39 Q4.C
N$8  (via drill 0.3)
  Top 0.406: v30.8,15.56 29.84,16.51 LED2.C
  Bottom 0.406: R34.2 32.07,14.29 v30.8,15.56
N$10  (via drill 0.3)
  Bottom 0.406: IC8.2 46.67,41.27 46.67,33.97 v47.94,33.97 49.21,33.97 49.21,20.95 45.09,20.95 R28.2
N$11
  Top 0.406: IC5.3 R7.2 R9.2
N$12
  Bottom 0.406: R15.2 18.42,22.23 17.46,22.23 16.51,23.18 Q4.B
N$13
  Top 0.254: IC4.4 20,29.52 20.64,30.16 22.54,30.16 23.18,30.8 23.18,31.12 R7.1
N$14  (via drill 0.3)
  Bottom 0.406: IC9.2 3.81,41.27 3.81,36.83 v8.89,31.75 29.53,31.75 37.47,23.81 R29.2
N$15
  Top 0.406: R19.1 C9.1 40.64,26.04 IC6.8
N$17
  Top 0.61: R8.1 19.36,36.19 IC5.5
N$18  (via drill 0.3)
  Top 0.406: v15.24,18.41 13.97,18.41 C21.1
  Bottom 0.406: R30.1 13.97,18.41 v15.24,18.41
N$19
  Bottom 0.406: IC3.5 23.81,67.62 R4.1
N$23  (via drill 0.3)
  Top 0.406: v34.92,22.86 35.56,23.5 IC6.3
  Bottom 0.406: R16.1 C7.1 33.66,22.86 v34.92,22.86
N$24  (via drill 0.3)
  Top 0.406: R20.1 34.61,26.04 IC6.1 36.83,26.25 v36.83,26.99
  Bottom 0.406: v36.83,26.99 40.01,23.81 R17.2
N$25
  Top 0.406: R21.1 R20.2 33.97,23.18 34.92,24.13 35.24,24.45 35.56,24.77 IC6.2
N$28  (via drill 0.3)
  Top 0.406: IC7.24 41.43,4.6 45.09,8.26 v45.09,16.19 C16.1
  Bottom 0.406: v45.09,16.19 C16.1
N$31  (via drill 0.3)
  Top 0.406: v17.78,18.41 16.51,18.41 C22.1
  Bottom 0.406: R31.1 16.51,18.41 v17.78,18.41
N$32  (via drill 0.3)
  Top 0.406: IC7.27 40.71,7.69 41.91,8.89 41.91,12.7 38.42,16.19 v38.1,16.19 38.1,16.83 C20.1
  Bottom 0.406: C20.1 38.1,16.83 v38.1,16.19
N$36  (via drill 0.3)
  Top 0.406: IC7.26 41.18,6.89 43.18,8.89 43.18,12.7 40.01,15.88 v40.01,16.19 C8.1
  Bottom 0.406: v40.01,16.19 C8.1
N$38  (via drill 0.3)
  Top 0.406: v12.7,18.41 11.43,18.41 C23.1
  Bottom 0.406: R32.1 11.43,18.41 v12.7,18.41
N$39  (via drill 0.3)
  Top 0.406: IC6.5 v44.45,22.23
  Bottom 0.406: R22.1 C10.1 45.4,23.18 v44.45,22.23
N$40
  Top 0.406: R25.1 R24.2 45.41,23.5 IC6.6
N$41  (via drill 0.3)
  Top 0.406: IC7.25 41.65,6.09 44.13,8.57 44.13,13.02 42.55,14.61 v42.55,16.19 C11.1
  Bottom 0.406: v42.55,16.19 C11.1
N$42  (via drill 0.3)
  Top 0.406: IC6.7 v44.45,24.77 45.41,24.77 R24.1
  Bottom 0.406: v44.45,24.77 43.5,23.81 42.55,22.86 42.55,21.27 42.55,20 R23.2
SPI1-MISO  (via drill 0.3)
  Top 0.406: IC7.16 26.3,6.09 19.37,13.02 v16.51,13.02 7.94,13.02 KD.3
  Bottom 0.406: v16.51,13.02 R31.2
SPI1-MOSI  (via drill 0.3)
  Top 0.406: IC7.15 26.77,6.89 19.68,13.97 v13.97,13.97 9.53,13.97 KD.5
  Bottom 0.406: v13.97,13.97 R30.2
SPI1-SCK  (via drill 0.3)
  Top 0.406: IC7.17 26.52,4.6 19.05,12.06 v11.43,12.06 KD.1
  Bottom 0.406: v11.43,12.06 R32.2
VCC  (via drill 0.3)
  Top 0.406: v22.86,36.83 22.86,35.88 22.23,35.24 21.27,35.24 20.64,34.61 IC5.2 20.64,33.02 20.32,32.7 16.83,32.7 14.92,30.8 14.61,30.48 FAN.1 | IC2.2 29.84,39.37 30.16,39.69 32.07,39.69 C1.1 | v22.86,66.67 22.86,73.03 22.23,73.66 22.23,75.06 L1.4
  Top 0.61: PWR.1 24.77,81.28 22.86,81.28 | 22.86,81.28 18.41,81.28 17.78,80.64 17.78,76.83 18,76.61 L1.5 18.03,75.56 20.95,75.56 20.98,75.53 L1.4 21.62,75.53 21.59,75.56 17.14,75.56 14.61,73.03 14.61,51.12 16.51,49.21 20.95,49.21 22.86,47.31 22.86,44.45 C2.1 | C6.+ 22.86,84.26 22.86,81.28 | C2.1 | v22.86,36.83 C2.1 | v32.7,36.83 C1.1
  Bottom 0.406: D9.C 14.61,28.91 FAN.1 | C3.1 20.32,63.19 21.27,64.14 21.59,64.14 22.23,64.14 22.86,64.14 22.86,63.5 IC3.2 v22.86,66.67
  Bottom 0.61: v22.86,36.83 23.18,36.83 v32.7,36.83
  pour Top (no thermals): 32.38,87 21.59,87 14.61,80.01 14.61,73.03 22.86,73.03 22.86,78.74 24.13,80.01 27.94,80.01 32.38,84.45
XTAL  (via drill 0.3)
  Top 0.406: IC7.7 31.02,14.06 30.48,14.61 v29.21,14.61
  Bottom 0.406: v29.21,14.61 29.21,16.5 QG1.3

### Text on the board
Top: Kicker v8
tPlace: VCC | GND
Cooling: max: 20x20mm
